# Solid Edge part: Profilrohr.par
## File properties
Username: bmolnar
Dokumentum tartalom típus: 0
Author: bmolnar
Last saved by: bmolnar
Revision: 80
Sűrűség: 0,000 kg/m^3
Pontosság: 0,990
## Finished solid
Body 1: solid body, 63 faces, 178 edges, 112 vertices.
  Faces by surface: cylinder 33, plane 30
  Edges by curve: line 112, circle 66
Bounding box of the edges (mm): 36.000 x 33.400 x 36.000, from (-18, -24.15, -18) to (18, 9.25, 18).
Cylindrical faces by radius (mm): R0.2 x12, R0.5 x12, R3.775 x4, R4.5 x4, R10 x1
Planar faces by outward normal: +x 7, +y 1, +z 7, -x 7, -y 1, -z 7
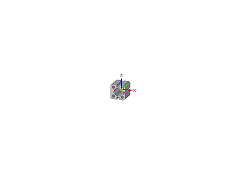
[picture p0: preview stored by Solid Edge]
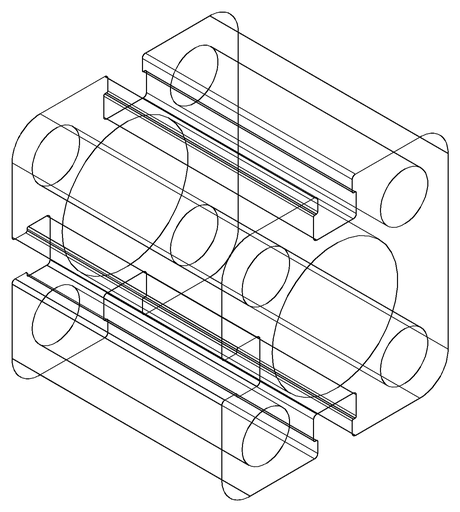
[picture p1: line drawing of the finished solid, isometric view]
